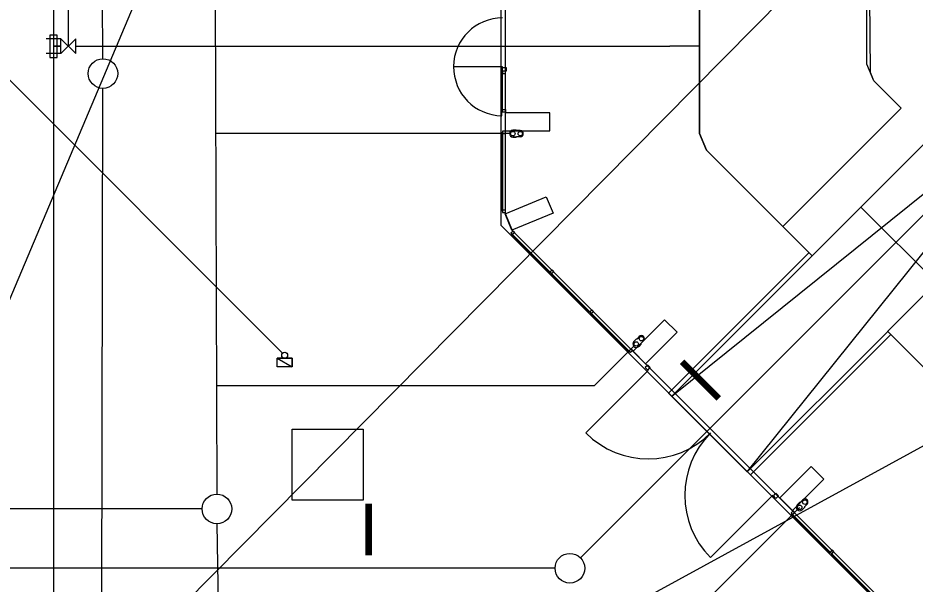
# Model space of a CAD drawing. Extents: x -264090 to -263500, y -1242327 to -1242030.
# Drawn here: x -263925.35 to -263895.07, y -1242239.48 to -1242220.38 of the extents above; entities that cross this region are included whole.
import ezdxf

# ---------------------------------------------------------------- set-up
doc = ezdxf.new("R2010")
doc.units = 0
for name, color, linetype in [('KFA_KOORD_SIT_a_IS_SEDA', 7, 'Continuous'), ('KFA_ZVS_NIVELACIA', 7, 'Continuous'), ('KFA_ZVS_SMERY_A_DLZKY', 7, 'Continuous')]:
    doc.layers.add(name, color=color, linetype=linetype)

msp = doc.modelspace()

# ---------------------------------------------------------------- linework, layer by layer
at = {"layer": 'KFA_KOORD_SIT_a_IS_SEDA'}
for p, q in [((-263922.479, -1242221.753), (-263922.731, -1242184.174)), ((-263924.143, -1242185.14), (-263924.143, -1242250.14)), ((-263918.755, -1242197.225), (-263918.632, -1242236.449)), ((-263908.893, -1242226.995), (-263908.893, -1242203.332)), ((-263902.343, -1242208.394), (-263902.343, -1242224.282)), ((-263896.578, -1242222.219), (-263896.693, -1242208.394)), ((-263923.643, -1242221.332), (-263923.643, -1242219.457)), ((-263923.893, -1242221.082), (-263924.393, -1242221.082)), ((-263924.018, -1242220.957), (-263924.268, -1242220.957)), ((-263924.268, -1242220.957), (-263924.268, -1242221.707)), ((-263924.018, -1242221.707), (-263924.018, -1242220.957)), ((-263923.893, -1242221.582), (-263923.893, -1242221.082)), ((-263923.893, -1242221.082), (-263923.393, -1242221.582)), ((-263923.393, -1242221.082), (-263923.893, -1242221.582)), ((-263923.393, -1242221.582), (-263923.393, -1242221.082)), ((-263924.143, -1242221.332), (-263923.893, -1242221.332)), ((-263923.893, -1242221.332), (-263924.143, -1242221.332)), ((-263923.393, -1242221.332), (-263903.343, -1242221.332)), ((-263889.023, -1242221.253), (-263906.365, -1242238.596)), ((-263902.343, -1242221.332), (-263903.343, -1242221.332)), ((-263923.893, -1242221.582), (-263924.393, -1242221.582)), ((-263924.268, -1242221.707), (-263924.018, -1242221.707)), ((-263916.414, -1242231.691), (-263926.24, -1242221.865)), ((-263908.993, -1242222.027), (-263910.643, -1242222.027)), ((-263909.018, -1242223.677), (-263909.018, -1242222.027)), ((-263908.993, -1242222.052), (-263908.993, -1242222.027)), ((-263908.993, -1242222.052), (-263908.873, -1242222.052)), ((-263908.993, -1242222.172), (-263908.993, -1242222.052)), ((-263908.873, -1242222.052), (-263908.873, -1242222.172)), ((-263909.018, -1242222.212), (-263909.018, -1242223.512)), ((-263908.993, -1242222.212), (-263909.018, -1242222.212)), ((-263908.893, -1242222.172), (-263908.993, -1242222.172)), ((-263908.993, -1242222.172), (-263908.993, -1242222.212)), ((-263908.873, -1242222.172), (-263908.993, -1242222.172)), ((-263908.993, -1242223.512), (-263908.993, -1242222.212)), ((-263908.993, -1242222.212), (-263908.993, -1242222.252)), ((-263908.993, -1242222.252), (-263908.893, -1242222.252)), ((-263908.893, -1242222.252), (-263908.893, -1242222.172)), ((-263896.463, -1242222.496), (-263896.578, -1242222.219)), ((-263895.535, -1242223.424), (-263896.463, -1242222.496)), ((-263922.54, -1242251.195), (-263922.477, -1242222.753)), ((-263909.018, -1242223.512), (-263908.993, -1242223.512)), ((-263908.993, -1242223.512), (-263908.993, -1242223.472)), ((-263908.993, -1242223.472), (-263908.893, -1242223.472)), ((-263908.993, -1242223.552), (-263908.993, -1242223.512)), ((-263908.893, -1242223.552), (-263908.993, -1242223.552)), ((-263908.893, -1242223.472), (-263908.893, -1242223.552)), ((-263899.53, -1242227.419), (-263895.535, -1242223.424)), ((-263907.398, -1242223.582), (-263908.898, -1242223.582)), ((-263908.898, -1242223.582), (-263908.898, -1242224.182)), ((-263907.398, -1242224.182), (-263907.398, -1242223.582)), ((-263908.532, -1242224.165), (-263908.643, -1242224.165)), ((-263908.518, -1242224.179), (-263908.532, -1242224.165)), ((-263908.393, -1242224.179), (-263908.518, -1242224.179)), ((-263908.718, -1242224.282), (-263918.67, -1242224.282)), ((-263909.018, -1242226.892), (-263909.018, -1242224.242)), ((-263909.018, -1242224.242), (-263908.993, -1242224.242)), ((-263908.893, -1242224.202), (-263908.993, -1242224.202)), ((-263908.993, -1242224.202), (-263908.993, -1242224.242)), ((-263908.993, -1242224.242), (-263908.993, -1242226.892)), ((-263908.993, -1242224.242), (-263908.993, -1242224.282)), ((-263908.993, -1242224.282), (-263908.893, -1242224.282)), ((-263908.898, -1242224.182), (-263907.398, -1242224.182)), ((-263908.893, -1242224.282), (-263908.893, -1242224.202)), ((-263908.643, -1242224.399), (-263908.532, -1242224.399)), ((-263908.532, -1242224.399), (-263908.643, -1242224.399)), ((-263908.518, -1242224.385), (-263908.532, -1242224.399)), ((-263908.393, -1242224.385), (-263908.518, -1242224.385)), ((-263902.343, -1242224.282), (-263902.113, -1242224.837)), ((-263902.113, -1242224.837), (-263899.53, -1242227.419)), ((-263908.903, -1242226.985), (-263907.518, -1242226.411)), ((-263907.518, -1242226.411), (-263907.288, -1242226.966)), ((-263908.993, -1242226.892), (-263909.018, -1242226.892)), ((-263908.893, -1242226.865), (-263908.993, -1242226.865)), ((-263908.993, -1242226.865), (-263908.993, -1242226.905)), ((-263908.893, -1242226.945), (-263908.893, -1242226.865)), ((-263908.993, -1242226.905), (-263908.993, -1242226.945)), ((-263908.993, -1242226.945), (-263908.893, -1242226.945)), ((-263908.674, -1242227.54), (-263908.903, -1242226.985)), ((-263908.893, -1242226.995), (-263908.663, -1242227.55)), ((-263907.288, -1242226.966), (-263908.674, -1242227.54)), ((-263908.709, -1242227.631), (-263908.638, -1242227.56)), ((-263908.68, -1242227.659), (-263908.709, -1242227.631)), ((-263908.685, -1242227.654), (-263908.703, -1242227.672)), ((-263908.703, -1242227.672), (-263907.395, -1242228.98)), ((-263907.377, -1242228.963), (-263908.685, -1242227.654)), ((-263908.652, -1242227.688), (-263908.68, -1242227.659)), ((-263908.663, -1242227.55), (-263895.135, -1242241.078)), ((-263908.581, -1242227.617), (-263908.652, -1242227.688)), ((-263908.638, -1242227.56), (-263908.581, -1242227.617)), ((-263907.395, -1242228.98), (-263907.377, -1242228.963)), ((-263907.39, -1242228.95), (-263907.319, -1242228.879)), ((-263907.361, -1242228.978), (-263907.39, -1242228.95)), ((-263907.363, -1242229.012), (-263907.345, -1242228.994)), ((-263906.055, -1242230.32), (-263907.363, -1242229.012)), ((-263907.333, -1242229.007), (-263907.361, -1242228.978)), ((-263907.345, -1242228.994), (-263906.037, -1242230.303)), ((-263907.262, -1242228.936), (-263907.333, -1242229.007)), ((-263907.319, -1242228.879), (-263907.262, -1242228.936)), ((-263906.046, -1242230.294), (-263905.975, -1242230.223)), ((-263905.975, -1242230.223), (-263905.918, -1242230.28)), ((-263906.037, -1242230.303), (-263906.055, -1242230.32)), ((-263906.017, -1242230.322), (-263906.046, -1242230.294)), ((-263906.019, -1242230.356), (-263906.001, -1242230.338)), ((-263904.711, -1242231.664), (-263906.019, -1242230.356)), ((-263905.989, -1242230.351), (-263906.017, -1242230.322)), ((-263906.001, -1242230.338), (-263904.693, -1242231.647)), ((-263905.918, -1242230.28), (-263905.989, -1242230.351)), ((-263903.526, -1242230.561), (-263904.586, -1242231.622)), ((-263903.101, -1242230.985), (-263903.526, -1242230.561)), ((-263904.376, -1242231.13), (-263904.465, -1242231.218)), ((-263904.162, -1242232.046), (-263903.101, -1242230.985)), ((-263904.533, -1242231.432), (-263905.894, -1242232.793)), ((-263904.484, -1242231.218), (-263904.563, -1242231.296)), ((-263904.465, -1242231.218), (-263904.484, -1242231.218)), ((-263904.397, -1242231.462), (-263904.319, -1242231.383)), ((-263904.319, -1242231.383), (-263904.397, -1242231.462)), ((-263904.231, -1242231.275), (-263904.319, -1242231.364)), ((-263904.319, -1242231.364), (-263904.319, -1242231.383)), ((-263904.726, -1242231.613), (-263904.656, -1242231.543)), ((-263904.698, -1242231.642), (-263904.726, -1242231.613)), ((-263904.693, -1242231.647), (-263904.711, -1242231.664)), ((-263904.67, -1242231.67), (-263904.698, -1242231.642)), ((-263904.599, -1242231.599), (-263904.67, -1242231.67)), ((-263904.656, -1242231.543), (-263904.599, -1242231.599)), ((-263904.586, -1242231.622), (-263904.162, -1242232.046)), ((-263916.593, -1242231.862), (-263916.093, -1242231.862)), ((-263916.593, -1242232.152), (-263916.593, -1242231.862)), ((-263916.593, -1242231.862), (-263916.093, -1242232.152)), ((-263916.593, -1242231.862), (-263916.093, -1242232.152)), ((-263916.093, -1242231.862), (-263916.593, -1242231.862)), ((-263916.093, -1242231.862), (-263916.093, -1242232.152)), ((-263916.093, -1242232.152), (-263916.093, -1242231.862)), ((-263916.093, -1242232.152), (-263916.593, -1242232.152)), ((-263904.074, -1242232.281), (-263906.177, -1242234.384)), ((-263904.091, -1242232.093), (-263904.176, -1242232.178)), ((-263904.176, -1242232.178), (-263904.091, -1242232.263)), ((-263904.006, -1242232.178), (-263904.091, -1242232.093)), ((-263904.091, -1242232.263), (-263904.006, -1242232.178)), ((-263904.091, -1242232.263), (-263904.074, -1242232.281)), ((-263905.894, -1242232.793), (-263918.643, -1242232.793)), ((-263916.093, -1242234.257), (-263913.693, -1242234.257)), ((-263916.093, -1242236.657), (-263916.093, -1242234.257)), ((-263913.693, -1242234.257), (-263913.693, -1242236.657)), ((-263899.631, -1242236.576), (-263898.571, -1242235.516)), ((-263898.571, -1242235.516), (-263898.147, -1242235.94)), ((-263898.147, -1242235.94), (-263899.207, -1242237.001)), ((-263899.866, -1242236.488), (-263901.97, -1242238.592)), ((-263899.849, -1242236.506), (-263899.764, -1242236.421)), ((-263899.764, -1242236.591), (-263899.849, -1242236.506)), ((-263899.764, -1242236.421), (-263899.679, -1242236.506)), ((-263899.679, -1242236.506), (-263899.764, -1242236.591)), ((-263899.207, -1242237.001), (-263899.631, -1242236.576)), ((-263913.693, -1242236.657), (-263916.093, -1242236.657)), ((-263898.965, -1242236.895), (-263902.238, -1242240.168)), ((-263898.969, -1242236.733), (-263899.047, -1242236.812)), ((-263898.949, -1242236.733), (-263898.969, -1242236.733)), ((-263898.861, -1242236.645), (-263898.949, -1242236.733)), ((-263898.715, -1242236.791), (-263898.804, -1242236.879)), ((-263898.804, -1242236.879), (-263898.804, -1242236.899)), ((-263919.13, -1242236.949), (-263926.43, -1242236.949)), ((-263899.018, -1242236.948), (-263902.238, -1242240.168)), ((-263899.185, -1242237.014), (-263899.255, -1242237.084)), ((-263899.255, -1242237.084), (-263899.227, -1242237.113)), ((-263899.232, -1242237.108), (-263899.25, -1242237.125)), ((-263899.25, -1242237.125), (-263897.942, -1242238.434)), ((-263897.924, -1242238.416), (-263899.232, -1242237.108)), ((-263899.227, -1242237.113), (-263899.199, -1242237.141)), ((-263899.199, -1242237.141), (-263899.128, -1242237.07)), ((-263899.128, -1242237.07), (-263899.185, -1242237.014)), ((-263898.804, -1242236.899), (-263898.882, -1242236.977)), ((-263898.882, -1242236.977), (-263898.804, -1242236.899)), ((-263918.378, -1242251.867), (-263918.622, -1242237.449)), ((-263897.865, -1242238.333), (-263897.936, -1242238.404)), ((-263897.936, -1242238.404), (-263897.908, -1242238.432)), ((-263897.88, -1242238.46), (-263897.809, -1242238.389)), ((-263897.809, -1242238.389), (-263897.865, -1242238.333)), ((-263897.942, -1242238.434), (-263897.924, -1242238.416)), ((-263897.908, -1242238.432), (-263897.88, -1242238.46)), ((-263897.888, -1242238.452), (-263897.906, -1242238.469)), ((-263897.906, -1242238.469), (-263896.598, -1242239.778)), ((-263896.58, -1242239.76), (-263897.888, -1242238.452)), ((-263907.219, -1242238.949), (-263926.43, -1242238.949))]:
    msp.add_line(p, q, dxfattribs=at)
for points in [[(-263794.893, -1242227.382), (-263808.968, -1242241.457), (-263894.968, -1242241.457), (-263909.043, -1242227.382), (-263909.043, -1242196.333), (-263914.143, -1242196.333), (-263914.143, -1242132.433), (-263909.043, -1242132.433), (-263909.043, -1242101.382), (-263894.968, -1242087.307), (-263808.968, -1242087.307), (-263794.893, -1242101.382), (-263794.893, -1242227.382)], [(-263816.02, -1242224.432), (-263887.916, -1242224.432), (-263888.26, -1242224.088), (-263889.254, -1242226.488), (-263890.391, -1242225.351), (-263894.351, -1242229.311), (-263896.896, -1242226.765), (-263892.937, -1242222.806), (-263894.073, -1242221.669), (-263891.673, -1242220.675), (-263892.018, -1242220.33), (-263892.018, -1242181.432), (-263893.618, -1242181.432), (-263893.618, -1242147.332), (-263892.018, -1242147.332), (-263892.018, -1242108.434)], [(-263898.543, -1242228.407), (-263902.112, -1242224.837), (-263902.343, -1242224.282), (-263902.343, -1242203.332), (-263909.043, -1242203.332)], [(-263891.673, -1242220.675), (-263894.073, -1242221.669), (-263892.937, -1242222.806), (-263898.544, -1242228.407)], [(-263895.995, -1242230.956), (-263890.391, -1242225.352), (-263889.254, -1242226.488), (-263888.26, -1242224.088), (-263891.673, -1242220.675)], [(-263903.277, -1242233.148), (-263900.731, -1242235.694), (-263890.333, -1242222.748), (-263903.277, -1242233.148)], [(-263898.65, -1242228.301), (-263903.39, -1242233.035), (-263900.629, -1242235.796), (-263895.875, -1242231.049)], [(-263898.544, -1242228.407), (-263903.281, -1242233.144), (-263900.731, -1242235.694), (-263895.982, -1242230.943)], [(-263807.942, -1242230.956), (-263811.512, -1242234.526), (-263812.068, -1242234.757), (-263891.868, -1242234.757), (-263892.424, -1242234.526), (-263895.994, -1242230.956)]]:
    msp.add_lwpolyline(points, dxfattribs=at)
msp.add_lwpolyline([(-263896.693, -1242208.394), (-263902.343, -1242208.394), (-263902.343, -1242224.282), (-263902.113, -1242224.837), (-263899.53, -1242227.419), (-263895.535, -1242223.424), (-263896.463, -1242222.496), (-263896.693, -1242221.942)], close=True, dxfattribs=at)
for centre, radius in [((-263922.476, -1242222.253), 0.5), ((-263908.643, -1242224.282), 0.075), ((-263908.393, -1242224.282), 0.075), ((-263904.303, -1242231.202), 0.075), ((-263904.48, -1242231.379), 0.075), ((-263916.343, -1242231.762), 0.1), ((-263918.63, -1242236.949), 0.5), ((-263918.63, -1242236.949), 0.5), ((-263898.965, -1242236.895), 0.075), ((-263898.788, -1242236.718), 0.075), ((-263906.719, -1242238.949), 0.5)]:
    msp.add_circle(centre, radius, dxfattribs=at)
for centre, radius, start, end in [((-263908.993, -1242222.027), 1.65, 90, 269.1318), ((-263908.643, -1242224.282), 0.117, 90, 270), ((-263908.393, -1242224.282), 0.103, 270, 90), ((-263904.303, -1242231.202), 0.103, 315, 135), ((-263904.48, -1242231.379), 0.117, 135, 315), ((-263904.074, -1242232.281), 2.975, 225.0001, 315.0001), ((-263899.866, -1242236.488), 2.975, 134.9999, 224.9999), ((-263898.965, -1242236.895), 0.117, 135, 315), ((-263898.788, -1242236.718), 0.103, 315, 135)]:
    msp.add_arc(centre, radius, start, end, dxfattribs=at)
at = {"layer": 'KFA_ZVS_NIVELACIA'}
for points in [[(-263916.904, -1242180.641), (-263925.798, -1242193.852), (-263930.312, -1242198.613), (-263934.768, -1242209.95), (-263940.766, -1242217.665), (-263943.387, -1242229.195), (-263938.661, -1242239.053), (-263943.261, -1242249.943), (-263937.6, -1242258.211)], [(-263937.6, -1242258.211), (-263940.179, -1242249.78), (-263938.22, -1242238.563), (-263938.948, -1242223.279), (-263930.232, -1242215.099), (-263920.849, -1242190.894), (-263913.063, -1242187.955), (-263916.904, -1242180.641)]]:
    msp.add_open_spline(points, degree=2, dxfattribs=at)
at = {"layer": 'KFA_ZVS_SMERY_A_DLZKY'}
for p, q in [((-263937.6, -1242258.211), (-263845.523, -1242040.303)), ((-263779.167, -1242098.021), (-263937.6, -1242258.211)), ((-263937.6, -1242258.211), (-263768.002, -1242165.53))]:
    msp.add_line(p, q, dxfattribs=at)

# ---------------------------------------------------------------- texts
at = {"layer": 'KFA_KOORD_SIT_a_IS_SEDA'}
msp.add_text('I', height=1.75, rotation=45.0119, dxfattribs=at).set_placement((-263901.924, -1242233.448))
msp.add_text('I', height=1.75, dxfattribs=at).set_placement((-263913.835, -1242238.519))

doc.saveas('drawing.dxf')
